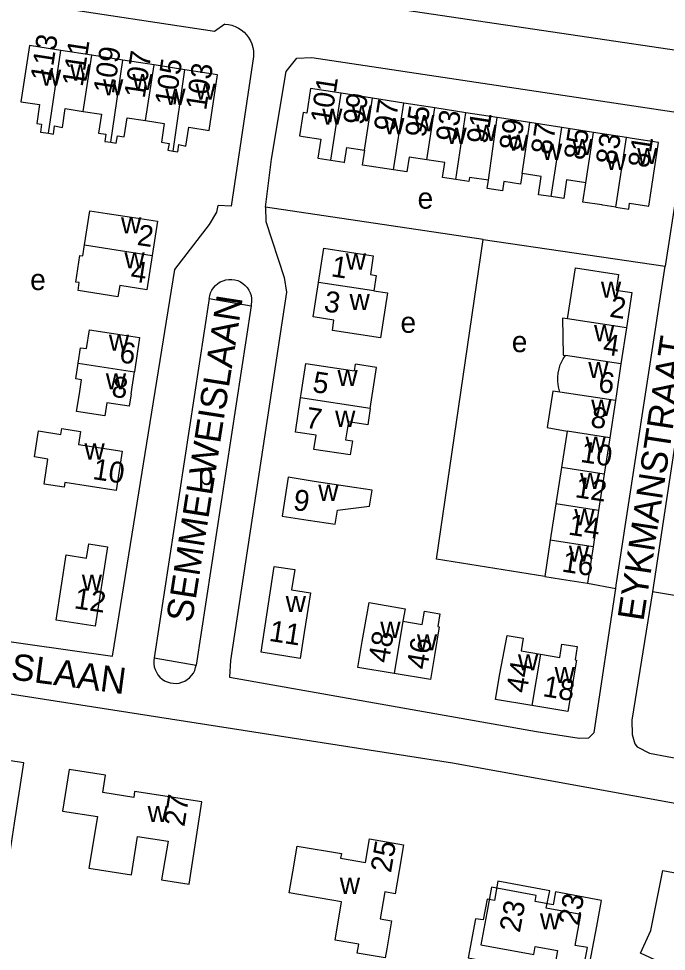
# Model space of a CAD drawing. Extents: x 161093 to 163177, y 379000 to 380904.
# Drawn here: x 161707.7 to 161831.1, y 380393.8 to 380571.5 of the extents above; entities that cross this region are included whole.
import ezdxf

# ---------------------------------------------------------------- set-up
doc = ezdxf.new("R2010")
doc.units = 0
for name, color, linetype in [('BLT_Basislijn', 7, 'Continuous'), ('BLT_Bebouwing', 7, 'Continuous'), ('BLT_Centroide', 7, 'Continuous'), ('BLT_Huisnummer', 7, 'Continuous'), ('BLT_Huisnummer_ tussenligend', 7, 'Continuous'), ('BLT_Huisnummer_zonder_bebouwing', 7, 'Continuous'), ('BLT_Onderverdeling_panden', 7, 'Continuous'), ('BLT_Plantopo', 7, 'Continuous'), ('BLT_Straatnaam', 7, 'Continuous')]:
    doc.layers.add(name, color=color, linetype=linetype)

msp = doc.modelspace()

# ---------------------------------------------------------------- linework, layer by layer
at = {"layer": 'BLT_Basislijn'}
for p, q in [((161765.74, 380575.56), (161840.27, 380564.46)), ((161796.21, 380529.43), (161754.75, 380535.6)), ((161796.21, 380529.43), (161830.91, 380524.37)), ((161837.43, 380521.48), (161828.52, 380462.26)), ((161744.01, 380518.15), (161733.54, 380449.72)), ((161751.98, 380516.81), (161741.52, 380448.3)), ((161744.01, 380518.15), (161751.98, 380516.81)), ((161816.11, 380463.95), (161821.51, 380462.92)), ((161834.99, 380461.19), (161828.52, 380462.26)), ((161660.66, 380449.92), (161790.41, 380429.73)), ((161733.54, 380449.72), (161741.52, 380448.3))]:
    msp.add_line(p, q, dxfattribs=at)
for points in [[(161746.98, 380570.46), (161745.04, 380569.05), (161681.04, 380578.78), (161678.56, 380580.9), (161677.21, 380580.9), (161676.31, 380580.49), (161675.65, 380579.76), (161675.17, 380578.54)], [(161746.98, 380570.46), (161747.66, 380570.39), (161748.32, 380570.24), (161748.96, 380570.02), (161749.57, 380569.72), (161750.13, 380569.35), (161750.66, 380568.92), (161751.12, 380568.43), (161751.53, 380567.89), (161751.87, 380567.3), (161752.14, 380566.68), (161752.33, 380566.03), (161752.45, 380565.36), (161752.48, 380564.69), (161752.46, 380564.27)], [(161752.46, 380564.27), (161748.22, 380535.79), (161745.7, 380535.92)], [(161754.75, 380535.6), (161755.89, 380544.7), (161758.65, 380561.45), (161760.72, 380563.99), (161763.58, 380564.09), (161833.83, 380553.53), (161834.89, 380552.05), (161834.86, 380549.82), (161830.91, 380524.37)], [(161663.42, 380502.41), (161661.2, 380488.51), (161657.26, 380462.85), (161657.39, 380460.55), (161658.52, 380459.57), (161660.05, 380459.3), (161725.58, 380450.01), (161737.46, 380523.7), (161744.09, 380532.28), (161745.47, 380534.65), (161745.7, 380535.92)], [(161754.75, 380535.6), (161754.82, 380532.84), (161758.28, 380522.15), (161758.76, 380519.39), (161748.08, 380449.17), (161747.85, 380446.02), (161806.41, 380435.64), (161814.52, 380434.41), (161816.39, 380434.48), (161817.36, 380435.45), (161821.51, 380462.92)], [(161807.95, 380465.2), (161787.35, 380468.54), (161796.21, 380529.43)], [(161821.51, 380462.92), (161821.6, 380463.54), (161830.91, 380524.37)], [(161744.01, 380518.15), (161744.11, 380518.71), (161744.28, 380519.25), (161744.52, 380519.77), (161744.84, 380520.24), (161745.21, 380520.67), (161745.65, 380521.04), (161746.13, 380521.34), (161746.65, 380521.57), (161747.19, 380521.73), (161747.76, 380521.81), (161748.33, 380521.81), (161748.89, 380521.74), (161749.44, 380521.58), (161749.96, 380521.35), (161750.44, 380521.04), (161750.87, 380520.68), (161751.25, 380520.25), (161751.57, 380519.78), (161751.81, 380519.27), (161751.99, 380518.72), (161752.08, 380518.16), (161752.1, 380517.59), (161752.03, 380517.03), (161751.98, 380516.81)], [(161828.52, 380462.26), (161824.59, 380437.84), (161824.62, 380435.09), (161825.13, 380433.29), (161825.61, 380432.73), (161827.94, 380431.56), (161888.53, 380420.08), (161892.51, 380420.22), (161894.01, 380422.22), (161900, 380461.58), (161905.75, 380498.33), (161906.39, 380499.55), (161912.7, 380507.69), (161913.21, 380510.04)], [(161733.54, 380449.72), (161733.46, 380449.16), (161733.46, 380448.59), (161733.54, 380448.02), (161733.7, 380447.48), (161733.94, 380446.96), (161734.24, 380446.48), (161734.61, 380446.04), (161735.04, 380445.67), (161735.51, 380445.35), (161736.03, 380445.11), (161736.57, 380444.94), (161737.13, 380444.85), (161737.7, 380444.83), (161738.27, 380444.9), (161738.82, 380445.05), (161739.34, 380445.27), (161739.83, 380445.56), (161740.27, 380445.92), (161740.66, 380446.34), (161740.99, 380446.8), (161741.25, 380447.31), (161741.43, 380447.85), (161741.52, 380448.3)], [(161790.41, 380429.73), (161841.6, 380420.4), (161892.77, 380409.85), (161973.76, 380391.48), (162004.17, 380383.95)]]:
    msp.add_lwpolyline(points, dxfattribs=at)
at = {"layer": 'BLT_Bebouwing'}
for p, q in [((161721.65, 380564.54), (161715.76, 380565.45)), ((161727.54, 380563.62), (161721.65, 380564.54)), ((161733.52, 380562.69), (161727.54, 380563.62)), ((161739.39, 380561.78), (161733.52, 380562.69)), ((161775.16, 380556.35), (161769.16, 380557.28)), ((161781.09, 380555.43), (161775.16, 380556.35)), ((161787.03, 380554.51), (161781.09, 380555.43)), ((161792.95, 380553.59), (161787.03, 380554.51)), ((161798.9, 380552.67), (161792.95, 380553.59)), ((161805.14, 380551.7), (161798.9, 380552.67)), ((161811.19, 380550.76), (161805.14, 380551.7)), ((161817.24, 380549.82), (161811.19, 380550.76)), ((161823.52, 380548.85), (161817.24, 380549.82)), ((161823.53, 380512.6), (161822.48, 380505.74)), ((161822.48, 380505.74), (161821.61, 380500)), ((161729.11, 380500), (161729.75, 380504.21)), ((161761.44, 380499.26), (161761.55, 380500)), ((161821.42, 380498.73), (161820.34, 380491.65)), ((161821.61, 380500), (161821.42, 380498.73)), ((161812.23, 380492.89), (161811.16, 380485.96)), ((161820.34, 380491.65), (161819.28, 380484.72)), ((161811.16, 380485.96), (161810.09, 380479.04)), ((161819.28, 380484.72), (161818.22, 380477.8)), ((161810.09, 380479.04), (161809.02, 380472.12)), ((161818.22, 380477.8), (161817.17, 380470.88)), ((161809.02, 380472.12), (161807.95, 380465.2)), ((161724.6, 380470.86), (161722.29, 380455.74)), ((161817.17, 380470.88), (161816.11, 380463.95)), ((161714.87, 380456.87), (161716.77, 380469.32)), ((161722.29, 380455.74), (161714.87, 380456.87)), ((161717.3, 380428.43), (161716.08, 380420.52)), ((161724.24, 380427.35), (161717.3, 380428.43)), ((161723.72, 380424.02), (161724.24, 380427.35)), ((161729.62, 380423.1), (161723.72, 380424.02)), ((161729.8, 380424.26), (161729.62, 380423.1)), ((161742.62, 380422.26), (161729.8, 380424.26)), ((161741.86, 380417.32), (161742.62, 380422.26)), ((161716.08, 380420.52), (161722.7, 380419.5)), ((161722.7, 380419.5), (161721.1, 380409.64)), ((161740.21, 380406.57), (161741.86, 380417.32)), ((161729.21, 380408.38), (161730.34, 380415.65)), ((161730.34, 380415.65), (161736.16, 380414.74)), ((161736.16, 380414.74), (161734.94, 380407.39)), ((161721.1, 380409.64), (161729.21, 380408.38)), ((161734.94, 380407.39), (161740.21, 380406.57))]:
    msp.add_line(p, q, dxfattribs=at)
for points in [[(161715.76, 380565.45), (161713.3, 380565.83), (161709.75, 380566.37), (161709, 380561.43), (161708.13, 380555.68), (161711.69, 380555.14), (161711.14, 380551.51), (161712.06, 380551.37), (161711.84, 380549.9), (161713.39, 380549.67)], [(161737.15, 380546.27), (161738.04, 380546.14), (161738.25, 380547.5), (161739.56, 380547.23), (161740.11, 380550.81), (161743.99, 380550.22), (161745.6, 380560.81), (161739.39, 380561.78)], [(161769.16, 380557.28), (161763.33, 380558.19), (161762.61, 380553.51), (161761.91, 380553.61), (161761.23, 380549.18), (161761.93, 380549.07), (161765.29, 380548.55), (161764.73, 380544.89), (161767.2, 380544.51)], [(161713.39, 380549.67), (161714.31, 380549.52), (161714.54, 380551.06), (161716.02, 380550.77), (161716.56, 380554.36), (161720.02, 380553.83)], [(161720.02, 380553.83), (161723.48, 380553.3), (161722.93, 380549.71), (161724.32, 380549.49), (161724.11, 380548.11), (161725.26, 380547.94)], [(161725.26, 380547.94), (161726.31, 380547.78), (161726.52, 380549.18), (161727.82, 380548.96), (161728.37, 380552.6), (161731.9, 380552.07)], [(161731.9, 380552.07), (161735.43, 380551.53), (161734.89, 380547.94), (161736.35, 380547.72), (161736.15, 380546.43), (161737.15, 380546.27)], [(161821.49, 380535.61), (161823.96, 380535.23), (161824.13, 380536.35), (161827.81, 380535.78), (161828.25, 380538.69), (161829.67, 380547.9), (161824.62, 380548.67), (161823.52, 380548.85)], [(161767.2, 380544.51), (161769.67, 380544.13), (161769.81, 380544.11), (161770.25, 380546.98), (161773.64, 380546.46)], [(161779.13, 380542.68), (161773.24, 380543.59), (161773.68, 380546.45), (161773.64, 380546.46)], [(161785.51, 380544.6), (161782.11, 380545.12), (161781.68, 380542.29), (161779.13, 380542.68)], [(161790.99, 380540.85), (161788.46, 380541.23), (161788.9, 380544.08), (161785.51, 380544.6)], [(161803.65, 380541.99), (161803.34, 380539.99), (161800.18, 380540.48), (161799.9, 380538.67), (161797, 380539.12), (161797.24, 380540.7)], [(161809.16, 380537.59), (161806.76, 380537.96), (161807.29, 380541.43), (161803.65, 380541.99)], [(161797.24, 380540.7), (161793.63, 380541.26), (161793.51, 380540.46), (161790.99, 380540.85)], [(161815.77, 380540.21), (161812.12, 380540.77), (161811.57, 380537.22), (161809.16, 380537.59)], [(161821.49, 380535.61), (161819.02, 380535.99), (161818.85, 380536.01), (161815.25, 380536.56), (161815.77, 380540.21)], [(161720.25, 380528.38), (161721.24, 380534.86), (161724.55, 380534.39), (161729.2, 380533.68), (161734.14, 380532.93), (161733.14, 380526.35)], [(161733.14, 380526.35), (161732.15, 380519.85), (161726.95, 380520.64), (161726.62, 380518.52), (161719.01, 380519.68), (161719.24, 380521.2), (161718.61, 380521.29), (161719.38, 380526.38), (161719.94, 380526.3), (161720.25, 380528.38)], [(161764.84, 380521.24), (161765.83, 380527.76), (161770.77, 380527.01), (161775.28, 380526.32), (161774.74, 380522.77), (161775.86, 380522.59), (161775.41, 380519.63)], [(161812.33, 380514.3), (161813.81, 380524.01), (161822.05, 380522.76), (161821.59, 380519.79), (161824.56, 380519.34), (161823.53, 380512.6)], [(161767.79, 380514.06), (161763.83, 380514.67), (161764.84, 380521.24)], [(161775.41, 380519.63), (161777.98, 380519.24), (161776.68, 380510.68), (161767.48, 380512.09), (161767.79, 380514.06)], [(161812.33, 380514.3), (161811.33, 380514.46), (161811.5, 380507.41), (161811.92, 380507.35)], [(161719.06, 380505.83), (161719.51, 380508.8), (161720.62, 380508.63), (161721.17, 380512.21), (161725.8, 380511.5), (161730.75, 380510.75), (161729.75, 380504.21)], [(161719.26, 380500), (161719.67, 380502.71), (161718.61, 380502.86), (161719.06, 380505.83)], [(161761.55, 380500), (161762.44, 380505.81), (161771.69, 380504.4), (161771.88, 380505.67)], [(161810.84, 380500.34), (161810.56, 380501.35), (161810.44, 380502.38), (161810.44, 380503.2), (161810.51, 380503.98), (161810.71, 380504.78), (161810.93, 380505.57), (161811.5, 380506.68), (161811.92, 380507.35)], [(161774.71, 380497.25), (161775.9, 380505.06), (161771.88, 380505.67)], [(161810.84, 380500.34), (161809.51, 380500.55), (161808.44, 380493.58), (161812.23, 380492.89)], [(161729.11, 380500), (161728.75, 380497.66), (161724.48, 380498.31), (161724.11, 380495.84), (161718.74, 380496.66), (161719.26, 380500)], [(161774.71, 380497.25), (161774.22, 380494.08), (161770.53, 380494.65), (161770, 380491.23), (161771.31, 380491.05), (161770.89, 380488.38), (161763.96, 380489.41), (161764.37, 380492.11), (161760.44, 380492.72), (161761.44, 380499.26)], [(161711.48, 380492.94), (161715.73, 380492.26), (161715.91, 380493.38), (161719.46, 380492.82), (161719.07, 380490.35), (161727.45, 380489.07), (161726.31, 380481.61), (161716.48, 380483.11), (161716.34, 380482.22), (161712.55, 380482.79), (161713.28, 380487.59), (161710.7, 380488), (161711.48, 380492.94)], [(161764.02, 380483.34), (161759.08, 380484.11), (161757.93, 380476.73), (161762.87, 380475.97), (161768.04, 380475.17), (161768.45, 380477.85), (161774.58, 380478.58), (161775.05, 380481.63), (161771.61, 380482.16), (161764.02, 380483.34)], [(161716.77, 380469.32), (161720.63, 380468.73), (161721.04, 380471.41), (161724.6, 380470.86)], [(161762.12, 380454.56), (161761.36, 380449.61), (161753.89, 380450.77), (161756.42, 380467.11), (161760.31, 380466.51), (161759.71, 380462.65), (161763.29, 380462.1), (161762.12, 380454.56)], [(161807.95, 380465.2), (161811.17, 380464.71), (161816.11, 380463.95)], [(161779.24, 380446.75), (161772.35, 380447.89), (161773.17, 380452.83), (161774.49, 380460.23), (161781.33, 380459.04), (161780.89, 380456.67)], [(161780.89, 380456.67), (161784.62, 380456.05), (161785.04, 380458.57), (161787.99, 380458.08), (161787.59, 380455.67), (161787.86, 380455.62), (161787.01, 380450.53), (161786.19, 380445.59), (161779.24, 380446.75)], [(161805.5, 380440.6), (161798.6, 380441.75), (161799.42, 380446.68), (161800.77, 380453.95), (161803.86, 380453.44), (161803.46, 380451.02), (161807.13, 380450.41)], [(161807.13, 380450.41), (161810.81, 380449.79), (161811.23, 380452.34), (161814.17, 380451.85), (161813.75, 380449.33), (161813.99, 380449.29), (161812.36, 380439.46), (161805.5, 380440.6)], [(161706.91, 380418.21), (161707.91, 380424.73), (161708.67, 380429.67), (161698.88, 380431.17), (161698.13, 380426.22), (161697, 380418.63), (161695.75, 380410.07), (161701.55, 380409.19), (161702.05, 380412.46), (161705.94, 380411.87), (161706.91, 380418.21)], [(161780.23, 380409.16), (161779.48, 380404.76), (161777.49, 380405.09), (161776.62, 380399.96), (161778.75, 380399.6), (161777.84, 380394.26), (161777.55, 380392.52), (161772.2, 380393.43), (161772.5, 380395.17), (161768.02, 380395.93), (161769.25, 380403.22), (161759.24, 380404.92), (161759.92, 380408.92), (161760.76, 380413.85), (161769.21, 380412.41), (161769.06, 380411.53), (161773.83, 380410.72), (161774.59, 380415.19), (161781.07, 380414.09), (161780.23, 380409.16)], [(161839.43, 380390.57), (161836.32, 380387.06), (161831.95, 380389.65), (161832.38, 380390.56), (161826.21, 380393.44), (161828.21, 380397.72), (161830.44, 380409.21), (161837.61, 380407.82), (161836.09, 380399.83), (161837.52, 380399.51), (161847.35, 380397.66), (161849.01, 380406.11), (161856.01, 380404.78)], [(161817.88, 380398.55), (161818.8, 380403.47), (161810.01, 380405.11), (161809.55, 380402.65), (161806.14, 380403.28), (161806.35, 380404.42), (161797.84, 380406.01), (161796.92, 380401.1), (161795.79, 380395.03), (161805.87, 380393.16), (161806.16, 380394.71), (161810.4, 380393.92), (161809.88, 380391.11), (161816.27, 380389.92), (161817.88, 380398.55)]]:
    msp.add_lwpolyline(points, dxfattribs=at)
at = {"layer": 'BLT_Onderverdeling_panden'}
for p, q in [((161713.39, 380549.67), (161715.76, 380565.45)), ((161720.02, 380553.83), (161721.65, 380564.54)), ((161725.26, 380547.94), (161727.54, 380563.62)), ((161731.9, 380552.07), (161733.52, 380562.69)), ((161737.15, 380546.27), (161739.39, 380561.78)), ((161767.2, 380544.51), (161769.16, 380557.28)), ((161773.64, 380546.46), (161775.16, 380556.35)), ((161779.13, 380542.68), (161781.09, 380555.43)), ((161785.51, 380544.6), (161787.03, 380554.51)), ((161790.99, 380540.85), (161792.95, 380553.59)), ((161797.24, 380540.7), (161798.9, 380552.67)), ((161803.65, 380541.99), (161805.14, 380551.7)), ((161809.16, 380537.59), (161811.19, 380550.76)), ((161815.77, 380540.21), (161817.24, 380549.82)), ((161821.49, 380535.61), (161823.52, 380548.85)), ((161720.25, 380528.38), (161733.14, 380526.35)), ((161775.41, 380519.63), (161764.84, 380521.24)), ((161823.53, 380512.6), (161812.33, 380514.3)), ((161719.06, 380505.83), (161729.75, 380504.21)), ((161822.48, 380505.74), (161811.92, 380507.35)), ((161774.71, 380497.25), (161761.44, 380499.26)), ((161821.42, 380498.73), (161810.84, 380500.34)), ((161820.34, 380491.65), (161812.23, 380492.89)), ((161819.28, 380484.72), (161811.16, 380485.96)), ((161818.22, 380477.8), (161810.09, 380479.04)), ((161817.17, 380470.88), (161809.02, 380472.12)), ((161780.89, 380456.67), (161779.24, 380446.75)), ((161807.13, 380450.41), (161805.5, 380440.6))]:
    msp.add_line(p, q, dxfattribs=at)
at = {"layer": 'BLT_Plantopo'}
msp.add_lwpolyline([(161799.05, 380407.16), (161798.36, 380403.48), (161796.96, 380403.74), (161796.22, 380399.8), (161794.75, 380400), (161793.36, 380392.53), (161800.83, 380391.13), (161800.53, 380389.52), (161808.97, 380387.94), (161809.29, 380389.63), (161814.98, 380388.57), (161816.09, 380394.49), (161813.78, 380394.92), (161814.87, 380400.77), (161808.26, 380402.01), (161808.96, 380405.31)], close=True, dxfattribs=at)

# ---------------------------------------------------------------- texts
at = {"layer": 'BLT_Centroide'}
for s, p in [('w', (161717.52, 380559.7)), ('w', (161711.94, 380558.72)), ('w', (161729.39, 380557.89)), ('w', (161723.78, 380556.89)), ('w', (161741.38, 380556.05)), ('w', (161735.64, 380555.08)), ('w', (161765.55, 380551.3)), ('w', (161771.17, 380551.91)), ('w', (161777.36, 380549.48)), ('w', (161783.08, 380550.05)), ('w', (161789.22, 380547.64)), ('w', (161794.94, 380548.22)), ('w', (161800.98, 380546.34)), ('w', (161813.2, 380545.52)), ('w', (161807.42, 380544.59)), ('w', (161825.58, 380543.81)), ('w', (161819.64, 380542.67)), ('e', (161783.73, 380535.3)), ('w', (161727.2, 380530.59)), ('w', (161727.86, 380523.91)), ('w', (161770.04, 380523.69)), ('e', (161709.89, 380519.79)), ('w', (161818.67, 380518.31)), ('w', (161770.76, 380515.97)), ('e', (161780.47, 380511.63)), ('w', (161817.37, 380510.03)), ('w', (161724.89, 380508.22)), ('e', (161801.68, 380507.96)), ('w', (161816.26, 380503.03)), ('w', (161768.45, 380501.5)), ('w', (161724.31, 380500.84)), ('w', (161816.82, 380495.81)), ('w', (161768.01, 380493.72)), ('w', (161815.75, 380488.81)), ('w', (161720.23, 380487.5)), ('p', (161741.87, 380482.65)), ('w', (161814.69, 380481.88)), ('w', (161764.8, 380479.62)), ('w', (161813.62, 380474.97)), ('w', (161812.56, 380468.03)), ('w', (161719.73, 380462.5)), ('w', (161758.59, 380458.41)), ('w', (161776.62, 380453.5)), ('w', (161783.61, 380451.12)), ('w', (161802.86, 380447.31)), ('w', (161809.83, 380444.92)), ('w', (161732.27, 380418.41)), ('w', (161768.9, 380404.72)), ('w', (161807.05, 380397.97))]:
    msp.add_text(s, height=4, dxfattribs=at).set_placement(p)
at = {"layer": 'BLT_Huisnummer'}
for s, rotation, p in [('113', 81.3468, (161713.84, 380559.39)), ('107', 81.3459, (161731.71, 380556.2)), ('103', 81.355, (161743.42, 380553.9)), ('101', 81.2555, (161767.22, 380551.34)), ('97', 81.2643, (161779.29, 380549.86)), ('93', 81.263, (161791.09, 380547.9)), ('89', 81.2692, (161803.18, 380546.19)), ('85', 81.2655, (161815.52, 380544.41)), ('81', 81.2566, (161827.74, 380542.89)), ('2', 351.3521, (161730.12, 380528.41)), ('1', 351.3231, (161767.1, 380522.42)), ('4', 351.3383, (161728.87, 380521.51)), ('3', 351.327, (161765.72, 380515.76)), ('2', 351.3288, (161820.18, 380514.72)), ('6', 351.3505, (161726.72, 380506.05)), ('5', 351.469, (161763.55, 380500.39)), ('6', 351.3219, (161817.99, 380500.42)), ('8', 351.3253, (161725.25, 380499.51)), ('7', 351.1876, (161762.22, 380493.58)), ('10', 351.3254, (161814.62, 380487.05)), ('10', 351.3253, (161721.66, 380483.79)), ('9', 351.1876, (161759.86, 380477.94)), ('16', 351.3253, (161811.08, 380466.16)), ('12', 351.3252, (161718.11, 380459.18)), ('11', 351.1922, (161755.26, 380452.96)), ('48', 80.563, (161778.23, 380448.58)), ('46', 80.5735, (161785.53, 380447.33)), ('44', 80.568, (161804.51, 380442.85)), ('18', 350.5708, (161807.43, 380442.42)), ('27', 81.1632, (161739.27, 380417.41)), ('25', 80.3625, (161778.65, 380408.62)), ('23', 79.4273, (161814.42, 380398.53))]:
    msp.add_text(s, height=4, rotation=rotation, dxfattribs=at).set_placement(p)
at = {"layer": 'BLT_Huisnummer_ tussenligend'}
for s, rotation, p in [('111', 81.3459, (161719.88, 380558.41)), ('109', 81.3459, (161725.84, 380557.05)), ('105', 81.355, (161737.55, 380554.74)), ('99', 81.2643, (161773.42, 380551.12)), ('95', 81.263, (161785.23, 380548.74)), ('91', 81.2692, (161796.97, 380547.48)), ('87', 81.2655, (161809.23, 380545.45)), ('83', 81.2566, (161821.6, 380543.5)), ('4', 351.3288, (161818.91, 380507.59)), ('8', 351.3219, (161816.54, 380493.71)), ('12', 351.3254, (161813.58, 380480.34)), ('14', 351.3254, (161812.31, 380473.21))]:
    msp.add_text(s, height=4, rotation=rotation, dxfattribs=at).set_placement(p)
at = {"layer": 'BLT_Huisnummer_zonder_bebouwing'}
msp.add_text('23', height=4, rotation=79.4273, dxfattribs=at).set_placement((161803.2, 380397.21))
at = {"layer": 'BLT_Straatnaam'}
for s, height, rotation, p in [('SEMMELWEISLAAN', 4.9999, 81.1149, (161740.74, 380456.29)), ('EYKMANSTRAAT', 5, 81.319, (161826.76, 380456.56)), ('VESALIUSLAAN', 4.9999, 352.4794, (161678.07, 380449.33))]:
    msp.add_text(s, height=height, rotation=rotation, dxfattribs=at).set_placement(p)

doc.saveas('drawing.dxf')
